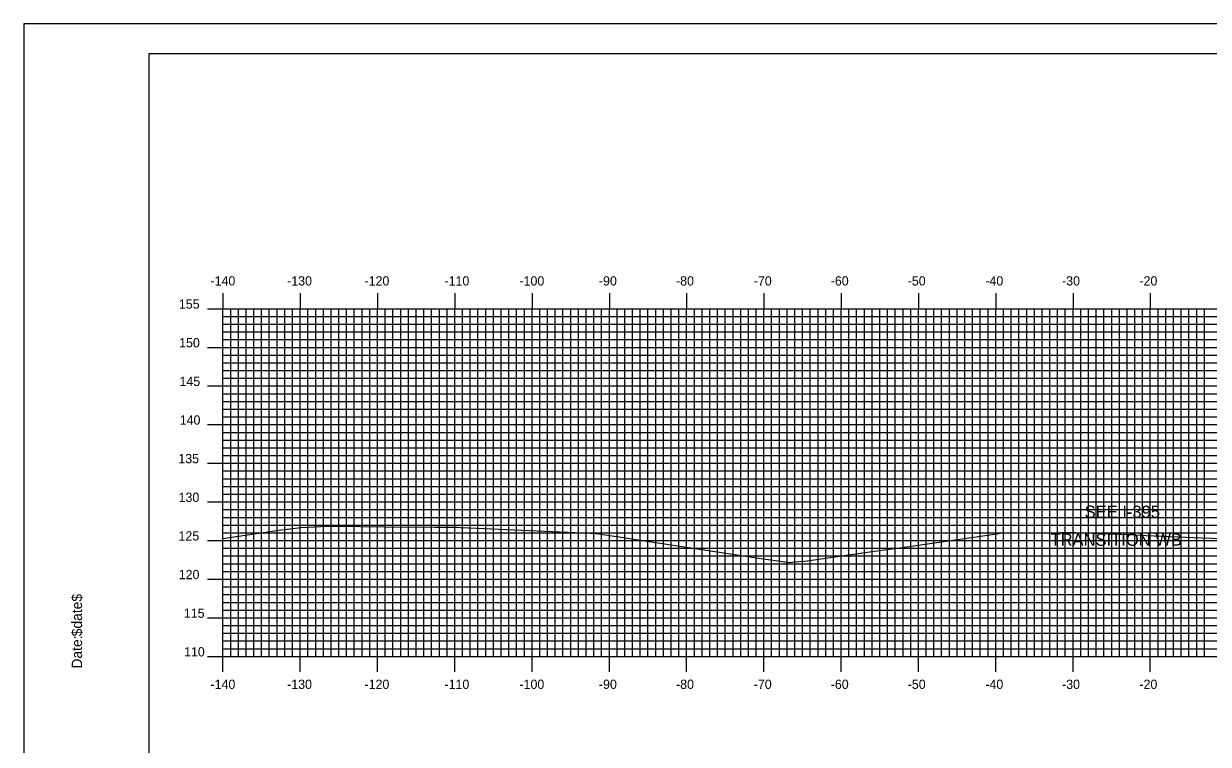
# Model space of a CAD drawing. Extents: x 854508 to 854851, y 364661 to 364881.
# Drawn here: x 854508 to 854661.3, y 364788 to 364881.3 of the extents above; entities that cross this region are included whole.
import ezdxf

# ---------------------------------------------------------------- set-up
doc = ezdxf.new("R2010")
doc.units = 0
for name, color, linetype in [('ANNOTATION', 7, 'Continuous'), ('BORDER', 7, 'Continuous'), ('H_V ANNOTATION', 7, 'Continuous'), ('M_Roadway_Centerline', 7, 'Continuous'), ('MAJOR', 7, 'Continuous'), ('MINOR', 7, 'Continuous'), ('PLOT BOUNDARY', 7, 'Continuous'), ('S_Roadway_Centerline', 7, 'Continuous')]:
    doc.layers.add(name, color=color, linetype=linetype)

msp = doc.modelspace()

# ---------------------------------------------------------------- linework, layer by layer
at = {"layer": 'BORDER'}
msp.add_lwpolyline([(854524.23, 364667.37), (854844.23, 364667.37), (854844.23, 364877.37), (854524.23, 364877.37)], close=True, dxfattribs=at)
at = {"layer": 'MAJOR'}
for p, q in [((854533.83, 364846.37), (854533.83, 364844.37)), ((854543.83, 364846.37), (854543.83, 364844.37)), ((854553.83, 364846.37), (854553.83, 364844.37)), ((854563.83, 364846.37), (854563.83, 364844.37)), ((854573.83, 364846.37), (854573.83, 364844.37)), ((854583.83, 364846.37), (854583.83, 364844.37)), ((854593.83, 364846.37), (854593.83, 364844.37)), ((854603.83, 364846.37), (854603.83, 364844.37)), ((854613.83, 364846.37), (854613.83, 364844.37)), ((854623.83, 364846.37), (854623.83, 364844.37)), ((854633.83, 364846.37), (854633.83, 364844.37)), ((854643.83, 364846.37), (854643.83, 364844.37)), ((854653.83, 364846.37), (854653.83, 364844.37)), ((854531.83, 364844.37), (854533.83, 364844.37)), ((854533.83, 364844.37), (854813.83, 364844.37)), ((854533.83, 364799.37), (854533.83, 364844.37)), ((854533.83, 364799.37), (854533.83, 364844.37)), ((854533.83, 364844.37), (854813.83, 364844.37)), ((854543.83, 364799.37), (854543.83, 364844.37)), ((854553.83, 364799.37), (854553.83, 364844.37)), ((854563.83, 364799.37), (854563.83, 364844.37)), ((854573.83, 364799.37), (854573.83, 364844.37)), ((854583.83, 364799.37), (854583.83, 364844.37)), ((854593.83, 364799.37), (854593.83, 364844.37)), ((854603.83, 364799.37), (854603.83, 364844.37)), ((854613.83, 364799.37), (854613.83, 364844.37)), ((854623.83, 364799.37), (854623.83, 364844.37)), ((854633.83, 364799.37), (854633.83, 364844.37)), ((854643.83, 364799.37), (854643.83, 364844.37)), ((854653.83, 364799.37), (854653.83, 364844.37)), ((854531.83, 364839.37), (854533.83, 364839.37)), ((854533.83, 364839.37), (854813.83, 364839.37)), ((854531.83, 364834.37), (854533.83, 364834.37)), ((854533.83, 364834.37), (854813.83, 364834.37)), ((854531.83, 364829.37), (854533.83, 364829.37)), ((854533.83, 364829.37), (854813.83, 364829.37)), ((854531.83, 364824.37), (854533.83, 364824.37)), ((854533.83, 364824.37), (854813.83, 364824.37)), ((854531.83, 364819.37), (854533.83, 364819.37)), ((854533.83, 364819.37), (854813.83, 364819.37)), ((854531.83, 364814.37), (854533.83, 364814.37)), ((854533.83, 364814.37), (854813.83, 364814.37)), ((854531.83, 364809.37), (854533.83, 364809.37)), ((854533.83, 364809.37), (854813.83, 364809.37)), ((854531.83, 364804.37), (854533.83, 364804.37)), ((854533.83, 364804.37), (854813.83, 364804.37)), ((854531.83, 364799.37), (854533.83, 364799.37)), ((854533.83, 364799.37), (854813.83, 364799.37)), ((854533.83, 364799.37), (854813.83, 364799.37)), ((854533.83, 364797.37), (854533.83, 364799.37)), ((854543.83, 364797.37), (854543.83, 364799.37)), ((854553.83, 364797.37), (854553.83, 364799.37)), ((854563.83, 364797.37), (854563.83, 364799.37)), ((854573.83, 364797.37), (854573.83, 364799.37)), ((854583.83, 364797.37), (854583.83, 364799.37)), ((854593.83, 364797.37), (854593.83, 364799.37)), ((854603.83, 364797.37), (854603.83, 364799.37)), ((854613.83, 364797.37), (854613.83, 364799.37)), ((854623.83, 364797.37), (854623.83, 364799.37)), ((854633.83, 364797.37), (854633.83, 364799.37)), ((854643.83, 364797.37), (854643.83, 364799.37)), ((854653.83, 364797.37), (854653.83, 364799.37))]:
    msp.add_line(p, q, dxfattribs=at)
at = {"layer": 'MINOR'}
for p, q in [((854534.83, 364799.37), (854534.83, 364844.37)), ((854535.83, 364799.37), (854535.83, 364844.37)), ((854536.83, 364799.37), (854536.83, 364844.37)), ((854537.83, 364799.37), (854537.83, 364844.37)), ((854538.83, 364799.37), (854538.83, 364844.37)), ((854539.83, 364799.37), (854539.83, 364844.37)), ((854540.83, 364799.37), (854540.83, 364844.37)), ((854541.83, 364799.37), (854541.83, 364844.37)), ((854542.83, 364799.37), (854542.83, 364844.37)), ((854544.83, 364799.37), (854544.83, 364844.37)), ((854545.83, 364799.37), (854545.83, 364844.37)), ((854546.83, 364799.37), (854546.83, 364844.37)), ((854547.83, 364799.37), (854547.83, 364844.37)), ((854548.83, 364799.37), (854548.83, 364844.37)), ((854549.83, 364799.37), (854549.83, 364844.37)), ((854550.83, 364799.37), (854550.83, 364844.37)), ((854551.83, 364799.37), (854551.83, 364844.37)), ((854552.83, 364799.37), (854552.83, 364844.37)), ((854554.83, 364799.37), (854554.83, 364844.37)), ((854555.83, 364799.37), (854555.83, 364844.37)), ((854556.83, 364799.37), (854556.83, 364844.37)), ((854557.83, 364799.37), (854557.83, 364844.37)), ((854558.83, 364799.37), (854558.83, 364844.37)), ((854559.83, 364799.37), (854559.83, 364844.37)), ((854560.83, 364799.37), (854560.83, 364844.37)), ((854561.83, 364799.37), (854561.83, 364844.37)), ((854562.83, 364799.37), (854562.83, 364844.37)), ((854564.83, 364799.37), (854564.83, 364844.37)), ((854565.83, 364799.37), (854565.83, 364844.37)), ((854566.83, 364799.37), (854566.83, 364844.37)), ((854567.83, 364799.37), (854567.83, 364844.37)), ((854568.83, 364799.37), (854568.83, 364844.37)), ((854569.83, 364799.37), (854569.83, 364844.37)), ((854570.83, 364799.37), (854570.83, 364844.37)), ((854571.83, 364799.37), (854571.83, 364844.37)), ((854572.83, 364799.37), (854572.83, 364844.37)), ((854574.83, 364799.37), (854574.83, 364844.37)), ((854575.83, 364799.37), (854575.83, 364844.37)), ((854576.83, 364799.37), (854576.83, 364844.37)), ((854577.83, 364799.37), (854577.83, 364844.37)), ((854578.83, 364799.37), (854578.83, 364844.37)), ((854579.83, 364799.37), (854579.83, 364844.37)), ((854580.83, 364799.37), (854580.83, 364844.37)), ((854581.83, 364799.37), (854581.83, 364844.37)), ((854582.83, 364799.37), (854582.83, 364844.37)), ((854584.83, 364799.37), (854584.83, 364844.37)), ((854585.83, 364799.37), (854585.83, 364844.37)), ((854586.83, 364799.37), (854586.83, 364844.37)), ((854587.83, 364799.37), (854587.83, 364844.37)), ((854588.83, 364799.37), (854588.83, 364844.37)), ((854589.83, 364799.37), (854589.83, 364844.37)), ((854590.83, 364799.37), (854590.83, 364844.37)), ((854591.83, 364799.37), (854591.83, 364844.37)), ((854592.83, 364799.37), (854592.83, 364844.37)), ((854594.83, 364799.37), (854594.83, 364844.37)), ((854595.83, 364799.37), (854595.83, 364844.37)), ((854596.83, 364799.37), (854596.83, 364844.37)), ((854597.83, 364799.37), (854597.83, 364844.37)), ((854598.83, 364799.37), (854598.83, 364844.37)), ((854599.83, 364799.37), (854599.83, 364844.37)), ((854600.83, 364799.37), (854600.83, 364844.37)), ((854601.83, 364799.37), (854601.83, 364844.37)), ((854602.83, 364799.37), (854602.83, 364844.37)), ((854604.83, 364799.37), (854604.83, 364844.37)), ((854605.83, 364799.37), (854605.83, 364844.37)), ((854606.83, 364799.37), (854606.83, 364844.37)), ((854607.83, 364799.37), (854607.83, 364844.37)), ((854608.83, 364799.37), (854608.83, 364844.37)), ((854609.83, 364799.37), (854609.83, 364844.37)), ((854610.83, 364799.37), (854610.83, 364844.37)), ((854611.83, 364799.37), (854611.83, 364844.37)), ((854612.83, 364799.37), (854612.83, 364844.37)), ((854614.83, 364799.37), (854614.83, 364844.37)), ((854615.83, 364799.37), (854615.83, 364844.37)), ((854616.83, 364799.37), (854616.83, 364844.37)), ((854617.83, 364799.37), (854617.83, 364844.37)), ((854618.83, 364799.37), (854618.83, 364844.37)), ((854619.83, 364799.37), (854619.83, 364844.37)), ((854620.83, 364799.37), (854620.83, 364844.37)), ((854621.83, 364799.37), (854621.83, 364844.37)), ((854622.83, 364799.37), (854622.83, 364844.37)), ((854624.83, 364799.37), (854624.83, 364844.37)), ((854625.83, 364799.37), (854625.83, 364844.37)), ((854626.83, 364799.37), (854626.83, 364844.37)), ((854627.83, 364799.37), (854627.83, 364844.37)), ((854628.83, 364799.37), (854628.83, 364844.37)), ((854629.83, 364799.37), (854629.83, 364844.37)), ((854630.83, 364799.37), (854630.83, 364844.37)), ((854631.83, 364799.37), (854631.83, 364844.37)), ((854632.83, 364799.37), (854632.83, 364844.37)), ((854634.83, 364799.37), (854634.83, 364844.37)), ((854635.83, 364799.37), (854635.83, 364844.37)), ((854636.83, 364799.37), (854636.83, 364844.37)), ((854637.83, 364799.37), (854637.83, 364844.37)), ((854638.83, 364799.37), (854638.83, 364844.37)), ((854639.83, 364799.37), (854639.83, 364844.37)), ((854640.83, 364799.37), (854640.83, 364844.37)), ((854641.83, 364799.37), (854641.83, 364844.37)), ((854642.83, 364799.37), (854642.83, 364844.37)), ((854644.83, 364799.37), (854644.83, 364844.37)), ((854645.83, 364799.37), (854645.83, 364844.37)), ((854646.83, 364799.37), (854646.83, 364844.37)), ((854647.83, 364799.37), (854647.83, 364844.37)), ((854648.83, 364799.37), (854648.83, 364844.37)), ((854649.83, 364799.37), (854649.83, 364844.37)), ((854650.83, 364799.37), (854650.83, 364844.37)), ((854651.83, 364799.37), (854651.83, 364844.37)), ((854652.83, 364799.37), (854652.83, 364844.37)), ((854654.83, 364799.37), (854654.83, 364844.37)), ((854655.83, 364799.37), (854655.83, 364844.37)), ((854656.83, 364799.37), (854656.83, 364844.37)), ((854657.83, 364799.37), (854657.83, 364844.37)), ((854658.83, 364799.37), (854658.83, 364844.37)), ((854659.83, 364799.37), (854659.83, 364844.37)), ((854660.83, 364799.37), (854660.83, 364844.37)), ((854533.83, 364843.37), (854813.83, 364843.37)), ((854533.83, 364843.37), (854535.84, 364843.37)), ((854533.83, 364842.37), (854813.83, 364842.37)), ((854533.83, 364842.37), (854535.84, 364842.37)), ((854533.83, 364841.37), (854813.83, 364841.37)), ((854533.83, 364841.37), (854535.84, 364841.37)), ((854533.83, 364840.37), (854813.83, 364840.37)), ((854533.83, 364840.37), (854535.84, 364840.37)), ((854533.83, 364838.37), (854813.83, 364838.37)), ((854533.83, 364838.37), (854535.84, 364838.37)), ((854533.83, 364837.37), (854813.83, 364837.37)), ((854533.83, 364837.37), (854535.84, 364837.37)), ((854533.83, 364836.37), (854813.83, 364836.37)), ((854533.83, 364836.37), (854535.84, 364836.37)), ((854533.83, 364835.37), (854813.83, 364835.37)), ((854533.83, 364835.37), (854535.84, 364835.37)), ((854533.83, 364833.37), (854813.83, 364833.37)), ((854533.83, 364833.37), (854535.84, 364833.37)), ((854533.83, 364832.37), (854813.83, 364832.37)), ((854533.83, 364832.37), (854535.84, 364832.37)), ((854533.83, 364831.37), (854813.83, 364831.37)), ((854533.83, 364831.37), (854535.84, 364831.37)), ((854533.83, 364830.37), (854813.83, 364830.37)), ((854533.83, 364830.37), (854535.84, 364830.37)), ((854533.83, 364828.37), (854813.83, 364828.37)), ((854533.83, 364828.37), (854535.84, 364828.37)), ((854533.83, 364827.37), (854813.83, 364827.37)), ((854533.83, 364827.37), (854535.84, 364827.37)), ((854533.83, 364826.37), (854813.83, 364826.37)), ((854533.83, 364826.37), (854535.84, 364826.37)), ((854533.83, 364825.37), (854813.83, 364825.37)), ((854533.83, 364825.37), (854535.84, 364825.37)), ((854533.83, 364823.37), (854813.83, 364823.37)), ((854533.83, 364823.37), (854535.84, 364823.37)), ((854533.83, 364822.37), (854813.83, 364822.37)), ((854533.83, 364822.37), (854535.84, 364822.37)), ((854533.83, 364821.37), (854813.83, 364821.37)), ((854533.83, 364821.37), (854535.84, 364821.37)), ((854533.83, 364820.37), (854813.83, 364820.37)), ((854533.83, 364820.37), (854535.84, 364820.37)), ((854533.83, 364818.37), (854813.83, 364818.37)), ((854533.83, 364818.37), (854535.84, 364818.37)), ((854533.83, 364817.37), (854813.83, 364817.37)), ((854533.83, 364817.37), (854535.84, 364817.37)), ((854533.83, 364816.37), (854813.83, 364816.37)), ((854533.83, 364816.37), (854535.84, 364816.37)), ((854533.83, 364815.37), (854813.83, 364815.37)), ((854533.83, 364815.37), (854535.84, 364815.37)), ((854533.83, 364813.37), (854813.83, 364813.37)), ((854533.83, 364813.37), (854535.84, 364813.37)), ((854533.83, 364812.37), (854813.83, 364812.37)), ((854533.83, 364812.37), (854535.84, 364812.37)), ((854533.83, 364811.37), (854813.83, 364811.37)), ((854533.83, 364811.37), (854535.84, 364811.37)), ((854533.83, 364810.37), (854813.83, 364810.37)), ((854533.83, 364810.37), (854535.84, 364810.37)), ((854533.83, 364808.37), (854813.83, 364808.37)), ((854533.83, 364808.37), (854535.84, 364808.37)), ((854533.83, 364807.37), (854813.83, 364807.37)), ((854533.83, 364807.37), (854535.84, 364807.37)), ((854533.83, 364806.37), (854813.83, 364806.37)), ((854533.83, 364806.37), (854535.84, 364806.37)), ((854533.83, 364805.37), (854813.83, 364805.37)), ((854533.83, 364805.37), (854535.84, 364805.37)), ((854533.83, 364803.37), (854813.83, 364803.37)), ((854533.83, 364803.37), (854535.84, 364803.37)), ((854533.83, 364802.37), (854813.83, 364802.37)), ((854533.83, 364802.37), (854535.84, 364802.37)), ((854533.83, 364801.37), (854813.83, 364801.37)), ((854533.83, 364801.37), (854535.84, 364801.37)), ((854533.83, 364800.37), (854813.83, 364800.37)), ((854533.83, 364800.37), (854535.84, 364800.37))]:
    msp.add_line(p, q, dxfattribs=at)
at = {"layer": 'PLOT BOUNDARY'}
msp.add_lwpolyline([(854508.05, 364661.25), (854848.05, 364661.25), (854848.05, 364881.25), (854508.05, 364881.25)], close=True, dxfattribs=at)
at = {"layer": 'S_Roadway_Centerline'}
msp.add_lwpolyline([(854533.83, 364814.65), (854541.07, 364815.69), (854543.92, 364816.06), (854546.49, 364816.19), (854548.34, 364816.24), (854554.86, 364816.14), (854561.24, 364816.1), (854563.75, 364816.09), (854564.12, 364816.08), (854564.61, 364816.05), (854575.47, 364815.59), (854581.33, 364815.34), (854581.54, 364815.33), (854581.76, 364815.31), (854585.08, 364814.86), (854586.99, 364814.54), (854603.17, 364812.07), (854607.13, 364811.54), (854607.67, 364811.63), (854609.12, 364811.69), (854617.82, 364812.94), (854620.37, 364813.28), (854621.13, 364813.38), (854633.99, 364815.25), (854634.67, 364815.36), (854642.18, 364815.42), (854644.17, 364815.39), (854650.84, 364815.16), (854651.18, 364815.15), (854653.31, 364815.03), (854660.46, 364814.7), (854678.65, 364814.12)], dxfattribs=at)

# ---------------------------------------------------------------- texts
at = {"layer": 'ANNOTATION'}
for s, p in [('SEE I-395 ', (854645.33, 364817.29)), ('TRANSITION WB', (854640.92, 364813.69))]:
    msp.add_text(s, height=1.6, dxfattribs=at).set_placement(p)
at = {"layer": 'BORDER'}
for s, p in [('$date$', (854515.6, 364801.98)), ('Date:', (854515.6, 364797.8))]:
    msp.add_text(s, height=1.339, rotation=90, dxfattribs=at).set_placement(p)
at = {"layer": 'H_V ANNOTATION'}
for s, p in [('-140', (854532.22, 364847.37)), ('-130', (854542.14, 364847.37)), ('-120', (854552.15, 364847.37)), ('-110', (854562.5, 364847.37)), ('-100', (854572.2, 364847.37)), ('-90', (854582.48, 364847.37)), ('-80', (854592.46, 364847.37)), ('-70', (854602.52, 364847.37)), ('-60', (854612.48, 364847.37)), ('-50', (854622.44, 364847.37)), ('-40', (854632.48, 364847.37)), ('-30', (854642.41, 364847.37)), ('-20', (854652.42, 364847.37)), ('155', (854528.13, 364844.37)), ('150', (854528.16, 364839.37)), ('145', (854528.21, 364834.37)), ('140', (854528.24, 364829.37)), ('135', (854528.06, 364824.37)), ('130', (854528.09, 364819.37)), ('125', (854528.08, 364814.37)), ('120', (854528.11, 364809.37)), ('115', (854528.77, 364804.37)), ('110', (854528.8, 364799.37)), ('-140', (854532.22, 364795.17)), ('-130', (854542.14, 364795.17)), ('-120', (854552.15, 364795.17)), ('-110', (854562.5, 364795.17)), ('-100', (854572.2, 364795.17)), ('-90', (854582.48, 364795.17)), ('-80', (854592.46, 364795.17)), ('-70', (854602.52, 364795.17)), ('-60', (854612.48, 364795.17)), ('-50', (854622.44, 364795.17)), ('-40', (854632.48, 364795.17)), ('-30', (854642.41, 364795.17)), ('-20', (854652.42, 364795.17))]:
    msp.add_text(s, height=1.2, dxfattribs=at).set_placement(p)
at = {"layer": 'M_Roadway_Centerline'}
for s, p in [('C', (854564.11, 364816.08)), ('L', (854564.12, 364816.07)), ('C', (854651.17, 364815.15)), ('L', (854651.18, 364815.15))]:
    msp.add_text(s, height=0.0146, dxfattribs=at).set_placement(p)
at = {"layer": 'MAJOR'}
msp.add_text('-', height=0.012, dxfattribs=at).set_placement((854533.82, 364799.37))

doc.saveas('drawing.dxf')
